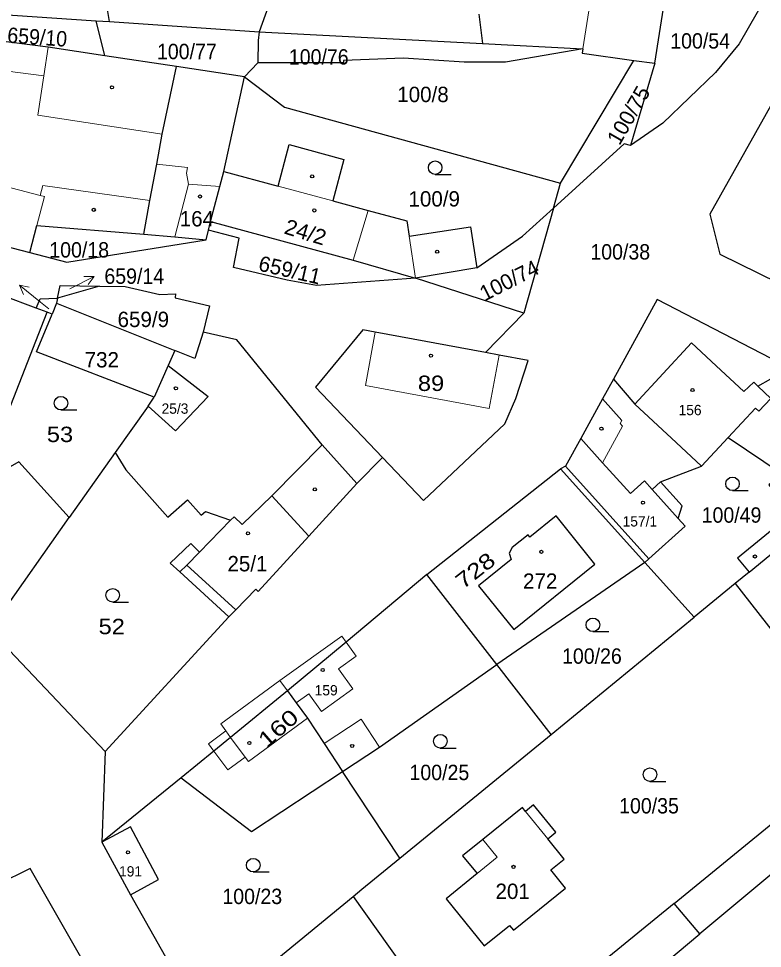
# Model space of a CAD drawing. Extents: x -758887 to -754328, y -1031688 to -1029144.
# Drawn here: x -756262.1 to -756179.9, y -1030550.3 to -1030447.4 of the extents above; entities that cross this region are included whole.
import ezdxf
from ezdxf.enums import TextEntityAlignment as Align

# ---------------------------------------------------------------- set-up
doc = ezdxf.new("R2010")
doc.units = 0
doc.header["$LTSCALE"] = 0.68
for name, color, linetype, lineweight in [('1', 7, 'Continuous', 25), ('3', 7, 'Continuous', 25), ('4', 7, 'Continuous', 13), ('5', 7, 'Continuous', 25), ('7', 7, 'Continuous', 13)]:
    doc.layers.add(name, color=color, linetype=linetype, lineweight=lineweight)
doc.layers.add('2', color=7, linetype='Continuous')

msp = doc.modelspace()

# ---------------------------------------------------------------- linework, layer by layer
at = {"layer": '1'}
for p, q in [((-756252.05, -1030447.75), (-756254.19, -1030434.42)), ((-756191.78, -1030452.34), (-756190.23, -1030442.57)), ((-756211.22, -1030446.93), (-756210.83, -1030450.16)), ((-756253.5, -1030447.65), (-756252.05, -1030447.75)), ((-756252.57, -1030451.52), (-756253.5, -1030447.65)), ((-756252.05, -1030447.75), (-756235.5, -1030448.86)), ((-756235.5, -1030448.86), (-756210.83, -1030450.16)), ((-756210.83, -1030450.16), (-756199.73, -1030450.74)), ((-756199.73, -1030450.74), (-756208.26, -1030452.22)), ((-756244.63, -1030452.72), (-756252.57, -1030451.52)), ((-756202.19, -1030465.6), (-756194.07, -1030452.03)), ((-756194.07, -1030452.03), (-756191.78, -1030452.34)), ((-756191.78, -1030452.34), (-756194.45, -1030461.45)), ((-756194.45, -1030461.45), (-756195.15, -1030461.28)), ((-756211.43, -1030474.98), (-756218.21, -1030476.12)), ((-756206.24, -1030480.01), (-756218.21, -1030476.12)), ((-756253.14, -1030477.01), (-756257.78, -1030478.35)), ((-756257.89, -1030478.9), (-756258.39, -1030480.1)), ((-756257.78, -1030478.35), (-756257.89, -1030478.9)), ((-756257.89, -1030478.9), (-756244.8, -1030484.13)), ((-756258.39, -1030480.1), (-756258.94, -1030479.89)), ((-756240.98, -1030479.17), (-756241.67, -1030482.11)), ((-756206.24, -1030480.01), (-756210.49, -1030484.35)), ((-756244.8, -1030484.13), (-756245.54, -1030485.8)), ((-756245.54, -1030485.8), (-756247.1, -1030489.29)), ((-756180.37, -1030488.07), (-756176.86, -1030486.08)), ((-756196.35, -1030487.29), (-756193.99, -1030490.05)), ((-756247.77, -1030490.28), (-756247.1, -1030489.29)), ((-756183.66, -1030493.75), (-756177.71, -1030497.78)), ((-756251.42, -1030495.41), (-756256.49, -1030502.6)), ((-756221.88, -1030495.96), (-756224.71, -1030498.85)), ((-756216.97, -1030508.91), (-756202.19, -1030497.2)), ((-756265.25, -1030515.03), (-756256.49, -1030502.6)), ((-756182.88, -1030509.9), (-756187.42, -1030513.62)), ((-756252.53, -1030528.46), (-756238.84, -1030513.59)), ((-756265.25, -1030515.03), (-756252.53, -1030528.46)), ((-756189.64, -1030545.27), (-756168.68, -1030528.11)), ((-756252.53, -1030528.46), (-756252.88, -1030538.51)), ((-756244.13, -1030531.38), (-756252.88, -1030538.51)), ((-756219.95, -1030540.28), (-756226.27, -1030530.68)), ((-756165.35, -1030530.67), (-756186.8, -1030548.66)), ((-756252.88, -1030538.51), (-756249.73, -1030544.32)), ((-756249.73, -1030544.32), (-756241.86, -1030558.24)), ((-756241.86, -1030558.24), (-756225.09, -1030544.5)), ((-756225.09, -1030544.5), (-756219.82, -1030551.93))]:
    msp.add_line(p, q, dxfattribs=at)
for points in [[(-756236.98, -1030430.71), (-756234.01, -1030444.73), (-756235.5, -1030448.86)], [(-756177.49, -1030439.12), (-756179.45, -1030444.96), (-756182.43, -1030450.22), (-756185.07, -1030453.38), (-756190.89, -1030458.98), (-756194.45, -1030461.45)], [(-756291.6, -1030443.2), (-756291.13, -1030445.14), (-756286.88, -1030445.42), (-756267.13, -1030446.74), (-756253.5, -1030447.65)], [(-756148.68, -1030456.69), (-756171.73, -1030444.13), (-756185.68, -1030469.03), (-756184.6, -1030473.45), (-756176.03, -1030477.68)], [(-756252.57, -1030451.52), (-756258.83, -1030450.57), (-756266.65, -1030449.57), (-756272.45, -1030448.6), (-756277.96, -1030447.75), (-756279.88, -1030447.72), (-756291.68, -1030447.55)], [(-756235.5, -1030448.86), (-756235.61, -1030449.82), (-756235.65, -1030452.29)], [(-756199.73, -1030450.74), (-756199.81, -1030451.24), (-756194.07, -1030452.03)], [(-756208.26, -1030452.22), (-756212.85, -1030452.24), (-756219.54, -1030451.78), (-756226.18, -1030452.03), (-756226.18, -1030452.31), (-756235.65, -1030452.29), (-756237.12, -1030453.86)], [(-756248.26, -1030471.27), (-756247.57, -1030467.54), (-756246.81, -1030463.51), (-756246.2, -1030460.21), (-756244.63, -1030452.72)], [(-756240.87, -1030469.85), (-756239.85, -1030465.99), (-756239.41, -1030464.32), (-756237.12, -1030453.86), (-756244.63, -1030452.72)], [(-756237.12, -1030453.86), (-756232.7, -1030457.21), (-756202.19, -1030465.6)], [(-756239.41, -1030464.32), (-756233.4, -1030465.94), (-756232.17, -1030461.34), (-756226.13, -1030463), (-756227.36, -1030467.57), (-756223.45, -1030468.62), (-756219.18, -1030469.78), (-756218.92, -1030471.47), (-756212.13, -1030470.44), (-756211.43, -1030474.98)], [(-756195.15, -1030461.28), (-756202.97, -1030468.38), (-756206.24, -1030480.01)], [(-756291.93, -1030464.52), (-756283.46, -1030467.28), (-756275.34, -1030469.53), (-756260.84, -1030473.29)], [(-756211.43, -1030474.98), (-756206.38, -1030471.48), (-756202.97, -1030468.38), (-756202.19, -1030465.6)], [(-756260.84, -1030473.29), (-756260.05, -1030470.29), (-756248.26, -1030471.27)], [(-756241.35, -1030471.87), (-756241.09, -1030470.81), (-756240.87, -1030469.85)], [(-756240.87, -1030469.85), (-756225.09, -1030474.12), (-756218.21, -1030476.12)], [(-756248.26, -1030471.27), (-756244.83, -1030471.56), (-756241.35, -1030471.87)], [(-756218.21, -1030476.12), (-756229.15, -1030476.92), (-756232.39, -1030476.36), (-756238.33, -1030474.96), (-756237.7, -1030471.7), (-756241.09, -1030470.81)], [(-756260.84, -1030473.29), (-756256.77, -1030474.34), (-756241.35, -1030471.87)], [(-756257.78, -1030478.35), (-756257.5, -1030476.93), (-756253.14, -1030477.01)], [(-756253.14, -1030477.01), (-756250.32, -1030477.06), (-756246.46, -1030477.93), (-756244.73, -1030477.87), (-756244.78, -1030478.31), (-756240.98, -1030479.17)], [(-756258.94, -1030479.89), (-756260.13, -1030479.44), (-756263.88, -1030478.04)], [(-756260.13, -1030479.44), (-756259.69, -1030478.42), (-756257.78, -1030478.35)], [(-756176.86, -1030486.08), (-756191.51, -1030478.5), (-756196.35, -1030487.29)], [(-756266.46, -1030499.12), (-756265.73, -1030497.26), (-756258.94, -1030479.89)], [(-756247.1, -1030489.29), (-756260.12, -1030484.26), (-756258.39, -1030480.1)], [(-756241.67, -1030482.11), (-756242.61, -1030485), (-756244.8, -1030484.13)], [(-756224.71, -1030498.85), (-756228.52, -1030494.56), (-756237.98, -1030482.93), (-756241.67, -1030482.11)], [(-756210.49, -1030484.35), (-756222.67, -1030482.1), (-756224.05, -1030481.85), (-756229.26, -1030488.18), (-756221.88, -1030495.96)], [(-756221.88, -1030495.96), (-756217.35, -1030500.73), (-756208.35, -1030492.24), (-756207.14, -1030489.44), (-756205.77, -1030485.22), (-756208.97, -1030484.63), (-756210.49, -1030484.35)], [(-756245.54, -1030485.8), (-756241.15, -1030489.22), (-756244.76, -1030493.01), (-756247.77, -1030490.28), (-756251.42, -1030495.41)], [(-756196.35, -1030487.29), (-756197.54, -1030489.47), (-756199.95, -1030493.85), (-756201.64, -1030496.92), (-756202.19, -1030497.2), (-756192.86, -1030507.57)], [(-756183.66, -1030493.75), (-756180.63, -1030490.5), (-756180.26, -1030490.84), (-756178.95, -1030489.42), (-756180.37, -1030488.07)], [(-756193.99, -1030490.05), (-756189.41, -1030494.31), (-756186.61, -1030496.9), (-756183.66, -1030493.75)], [(-756251.42, -1030495.41), (-756250.25, -1030497.33), (-756245.6, -1030502.56), (-756243.43, -1030500.63), (-756241.9, -1030502.35), (-756241.42, -1030501.92), (-756238.65, -1030502.9)], [(-756256.49, -1030502.6), (-756262.05, -1030496.44), (-756265.67, -1030498.5), (-756266.46, -1030499.12)], [(-756192.86, -1030507.57), (-756192.42, -1030507.18), (-756188.4, -1030503.57), (-756189.17, -1030502.71), (-756188.74, -1030501.32), (-756191.14, -1030498.64), (-756186.61, -1030496.9)], [(-756177.71, -1030497.78), (-756179.18, -1030498.98), (-756176.58, -1030502.15), (-756182.62, -1030507.1), (-756181.35, -1030508.64)], [(-756181.35, -1030508.64), (-756173.85, -1030502.5), (-756177.71, -1030497.78)], [(-756238.84, -1030513.59), (-756238.06, -1030512.79), (-756235.87, -1030510.53), (-756235.6, -1030510.78), (-756230.01, -1030504.65), (-756224.71, -1030498.85)], [(-756238.65, -1030502.9), (-756242.1, -1030506.42), (-756243.06, -1030505.47), (-756245.32, -1030507.64), (-756244.25, -1030508.62), (-756238.84, -1030513.59)], [(-756203.24, -1030526.59), (-756187.42, -1030513.62), (-756192.86, -1030507.57), (-756209.24, -1030518.86)], [(-756181.35, -1030508.64), (-756182.88, -1030509.9), (-756168.68, -1030528.11)], [(-756216.97, -1030508.91), (-756225.89, -1030516.37), (-756232.36, -1030521.78)], [(-756226.27, -1030530.68), (-756222.18, -1030527.98), (-756209.24, -1030518.86), (-756216.97, -1030508.91)], [(-756219.95, -1030540.28), (-756203.24, -1030526.59), (-756209.24, -1030518.86)], [(-756232.36, -1030521.78), (-756238.65, -1030526.91), (-756240.51, -1030528.43), (-756244.13, -1030531.38)], [(-756232.36, -1030521.78), (-756231.39, -1030523.1), (-756230.15, -1030524.79), (-756228.31, -1030527.59), (-756226.27, -1030530.68)], [(-756244.13, -1030531.38), (-756236.33, -1030537.31), (-756226.27, -1030530.68)], [(-756249.73, -1030544.32), (-756246.61, -1030542.63), (-756249.7, -1030536.79), (-756252.88, -1030538.51)], [(-756225.09, -1030544.5), (-756224.14, -1030543.72), (-756219.95, -1030540.28)], [(-756238.06, -1030581.25), (-756260.8, -1030541.42), (-756271.57, -1030546.71), (-756294.15, -1030557.1), (-756273.96, -1030597.77)], [(-756156.85, -1030540.84), (-756201.34, -1030571.62), (-756205.5, -1030564.34), (-756186.8, -1030548.66), (-756189.64, -1030545.27)], [(-756189.64, -1030545.27), (-756210.31, -1030562.19), (-756210.84, -1030564.8)]]:
    msp.add_lwpolyline(points, dxfattribs=at)
for points in [[(-756211.25, -1030510.17), (-756207.36, -1030514.98), (-756198.38, -1030507.74), (-756202.67, -1030502.42), (-756205.57, -1030504.77), (-756205.78, -1030504.52), (-756207.52, -1030505.91), (-756207.87, -1030506.55), (-756207.66, -1030507.25)], [(-756210.78, -1030538.2), (-756213.01, -1030540.01), (-756211.42, -1030541.98), (-756214.83, -1030544.77), (-756210.62, -1030549.97), (-756207.82, -1030547.71), (-756207.39, -1030548.24), (-756201.64, -1030543.58), (-756203.27, -1030541.56), (-756201.8, -1030540.37), (-756203.61, -1030538.13), (-756202.71, -1030537.41), (-756205.17, -1030534.37), (-756206.06, -1030535.1), (-756206.41, -1030534.67)]]:
    msp.add_lwpolyline(points, close=True, dxfattribs=at)
at = {"layer": '3'}
for p, q in [((-756216.043, -1030464.65), (-756214.293, -1030464.65)), ((-756257.403, -1030490.7), (-756255.653, -1030490.7)), ((-756183.183, -1030499.62), (-756181.433, -1030499.62)), ((-756251.683, -1030511.95), (-756249.933, -1030511.95)), ((-756198.613, -1030515.22), (-756196.863, -1030515.22)), ((-756215.473, -1030528.09), (-756213.723, -1030528.09)), ((-756192.303, -1030531.78), (-756190.553, -1030531.78)), ((-756236.153, -1030541.8), (-756234.403, -1030541.8))]:
    msp.add_line(p, q, dxfattribs=at)
for centre in [(-756216.0429, -1030463.8998), (-756257.4029, -1030489.9498), (-756183.1829, -1030498.8698), (-756251.6829, -1030511.1998), (-756198.6129, -1030514.4698), (-756215.4729, -1030527.3398), (-756192.3029, -1030531.0298), (-756236.1529, -1030541.0498)]:
    msp.add_circle(centre, 0.75, dxfattribs=at)
at = {"layer": '4'}
for p, q in [((-756199.73, -1030450.74), (-756197.21, -1030434.84)), ((-756258.83, -1030450.57), (-756259.31, -1030453.73)), ((-756259.97, -1030458.08), (-756246.2, -1030460.21)), ((-756259.7, -1030466.97), (-756273.73, -1030463.33)), ((-756259.41, -1030465.86), (-756259.7, -1030466.97)), ((-756259.41, -1030465.86), (-756247.57, -1030467.54)), ((-756227.36, -1030467.57), (-756233.4, -1030465.94)), ((-756260.05, -1030470.29), (-756259.21, -1030467.1)), ((-756259.21, -1030467.1), (-756259.7, -1030466.97)), ((-756223.45, -1030468.62), (-756225.09, -1030474.12)), ((-756218.92, -1030471.47), (-756218.21, -1030476.12)), ((-756223.76, -1030488), (-756222.67, -1030482.1)), ((-756187.73, -1030483.29), (-756193.99, -1030490.05)), ((-756185, -1030485.81), (-756187.73, -1030483.29)), ((-756181.92, -1030488.64), (-756185, -1030485.81)), ((-756180.84, -1030487.62), (-756181.92, -1030488.64)), ((-756180.37, -1030488.07), (-756180.84, -1030487.62)), ((-756197.54, -1030489.47), (-756195.4, -1030491.85)), ((-756195.4, -1030491.85), (-756195.6, -1030492.2)), ((-756195.6, -1030492.2), (-756195.33, -1030492.5)), ((-756197.54, -1030496.53), (-756195.33, -1030492.5)), ((-756199.95, -1030493.85), (-756197.54, -1030496.53)), ((-756234.09, -1030500.21), (-756228.52, -1030494.56)), ((-756201.64, -1030496.92), (-756192.42, -1030507.18)), ((-756197.54, -1030496.53), (-756194.47, -1030499.95)), ((-756192.91, -1030498.55), (-756194.47, -1030499.95)), ((-756192.91, -1030498.55), (-756192.07, -1030499.48)), ((-756242.1, -1030506.42), (-756243.49, -1030507.85)), ((-756243.49, -1030507.85), (-756244.25, -1030508.62)), ((-756243.49, -1030507.85), (-756238.06, -1030512.79)), ((-756233.2, -1030520.64), (-756226.37, -1030515.71)), ((-756225.89, -1030516.37), (-756226.37, -1030515.71)), ((-756224.76, -1030517.93), (-756225.89, -1030516.37)), ((-756239.73, -1030525.43), (-756233.2, -1030520.64)), ((-756233.2, -1030520.64), (-756232.36, -1030521.78)), ((-756231.39, -1030523.1), (-756230.02, -1030522.1)), ((-756230.02, -1030522.1), (-756228.61, -1030524.05)), ((-756236.68, -1030529.59), (-756230.15, -1030524.79)), ((-756224.22, -1030524.89), (-756228.31, -1030527.59)), ((-756222.18, -1030527.98), (-756224.22, -1030524.89)), ((-756239.17, -1030526.2), (-756241.1, -1030527.62)), ((-756239.17, -1030526.2), (-756239.73, -1030525.43)), ((-756239.17, -1030526.2), (-756238.65, -1030526.91)), ((-756238.65, -1030526.91), (-756237.04, -1030529.1)), ((-756241.1, -1030527.62), (-756240.51, -1030528.43)), ((-756240.51, -1030528.43), (-756238.97, -1030530.52)), ((-756238.97, -1030530.52), (-756237.04, -1030529.1)), ((-756237.04, -1030529.1), (-756236.68, -1030529.59)), ((-756206.06, -1030535.1), (-756203.61, -1030538.13))]:
    msp.add_line(p, q, dxfattribs=at)
for points in [[(-756267.06, -1030452.74), (-756259.31, -1030453.73), (-756259.97, -1030458.08)], [(-756246.81, -1030463.51), (-756243.4, -1030463.89), (-756243.52, -1030464.52), (-756243.29, -1030465.71)], [(-756244.83, -1030471.56), (-756243.29, -1030465.71), (-756239.85, -1030465.99)], [(-756223.76, -1030488), (-756210.06, -1030490.53), (-756208.97, -1030484.63)], [(-756191.14, -1030498.64), (-756192.07, -1030499.48), (-756189.17, -1030502.71)], [(-756238.65, -1030502.9), (-756238.27, -1030502.52), (-756237.36, -1030503.38), (-756234.09, -1030500.21), (-756230.01, -1030504.65)], [(-756228.61, -1030524.05), (-756225.13, -1030521.53), (-756226.71, -1030519.34), (-756224.76, -1030517.93)], [(-756211.42, -1030541.98), (-756209.18, -1030540.17), (-756210.78, -1030538.2)]]:
    msp.add_lwpolyline(points, dxfattribs=at)
at = {"layer": '5'}
for centre in [(-756251.7668, -1030455.0092), (-756229.6368, -1030464.8592), (-756242.0368, -1030467.0892), (-756253.7768, -1030468.5592), (-756229.4068, -1030468.6292), (-756215.8268, -1030473.1992), (-756216.5068, -1030484.6892), (-756244.6968, -1030488.2992), (-756187.6068, -1030488.4992), (-756197.6668, -1030492.7692), (-756229.3468, -1030499.4792), (-756193.0768, -1030500.9592), (-756236.7368, -1030504.3492), (-756204.3068, -1030506.3892), (-756180.7068, -1030506.9092), (-756228.4768, -1030519.4692), (-756236.5768, -1030527.5292), (-756225.2168, -1030527.8592), (-756249.9968, -1030539.6292), (-756207.3868, -1030541.2392)]:
    msp.add_circle(centre, 0.175, dxfattribs=at)
at = {"layer": '7'}
for p, q in [((-756253.746, -1030475.928), (-756254.866, -1030475.936)), ((-756262.002, -1030476.891), (-756261.539, -1030477.911))]:
    msp.add_line(p, q, dxfattribs=at)
for points in [[(-756256.42, -1030477.29), (-756253.746, -1030475.928), (-756254.411, -1030476.828)], [(-756258.73, -1030479.53), (-756259.67, -1030478.78), (-756262.002, -1030476.891), (-756260.909, -1030477.133)]]:
    msp.add_lwpolyline(points, dxfattribs=at)

# ---------------------------------------------------------------- texts
at = {"layer": '2'}
for s, rotation, width, p in [('659/10', 356, 0.95, (-756260.0788, -1030450.3004)), ('24/2', 343, 1.05, (-756230.622, -1030471.8429)), ('728', 38, 1.25, (-756211.0868, -1030509.1165)), ('160', 41, 1.3, (-756232.8296, -1030526.5481))]:
    msp.add_text(s, height=1.7, rotation=rotation, dxfattribs=dict(at, width=width)).set_placement(p, align=Align.CENTER)
for s, width, p in [('100/54', 0.95, (-756186.759, -1030450.73)), ('100/77', 0.95, (-756243.489, -1030451.9)), ('100/76', 0.95, (-756228.909, -1030452.5)), ('100/18', 0.95, (-756255.389, -1030473.84)), ('100/38', 0.95, (-756195.589, -1030474.06)), ('659/14', 0.95, (-756249.299, -1030476.75)), ('89', 1.15, (-756216.5, -1030488.6)), ('53', 1.15, (-756257.51, -1030494.25)), ('100/49', 0.95, (-756183.289, -1030503.17)), ('52', 1.15, (-756251.79, -1030515.5)), ('100/26', 0.95, (-756198.719, -1030518.77)), ('100/25', 0.95, (-756215.579, -1030531.64)), ('100/35', 0.95, (-756192.409, -1030535.33)), ('100/23', 0.95, (-756236.259, -1030545.35))]:
    msp.add_text(s, height=1.7, dxfattribs=dict(at, width=width)).set_placement(p, align=Align.CENTER)
for s, height, p in [('100/8', 1.7, (-756217.39, -1030456.65)), ('100/9', 1.7, (-756216.15, -1030468.2)), ('164', 1.7, (-756242.379, -1030470.4)), ('659/9', 1.7, (-756248.3, -1030481.53)), ('732', 1.7, (-756252.889, -1030486)), ('25/3', 1.14, (-756244.799, -1030491.12)), ('156', 1.14, (-756187.87, -1030491.28)), ('157/1', 1.14, (-756193.419, -1030503.59)), ('25/1', 1.7, (-756236.79, -1030508.55)), ('272', 1.7, (-756204.439, -1030510.48)), ('159', 1.14, (-756228.09, -1030522.27)), ('191', 1.14, (-756249.71, -1030542.3)), ('201', 1.7, (-756207.479, -1030544.79))]:
    msp.add_text(s, height=height, dxfattribs=at).set_placement(p, align=Align.CENTER)
for s, rotation, p in [('100/75', 60, (-756193.9394, -1030458.5205)), ('659/11', 347, (-756232.2937, -1030476.047)), ('100/74', 27, (-756207.4764, -1030477.1262))]:
    msp.add_text(s, height=1.7, rotation=rotation, dxfattribs=at).set_placement(p, align=Align.CENTER)

doc.saveas('drawing.dxf')
